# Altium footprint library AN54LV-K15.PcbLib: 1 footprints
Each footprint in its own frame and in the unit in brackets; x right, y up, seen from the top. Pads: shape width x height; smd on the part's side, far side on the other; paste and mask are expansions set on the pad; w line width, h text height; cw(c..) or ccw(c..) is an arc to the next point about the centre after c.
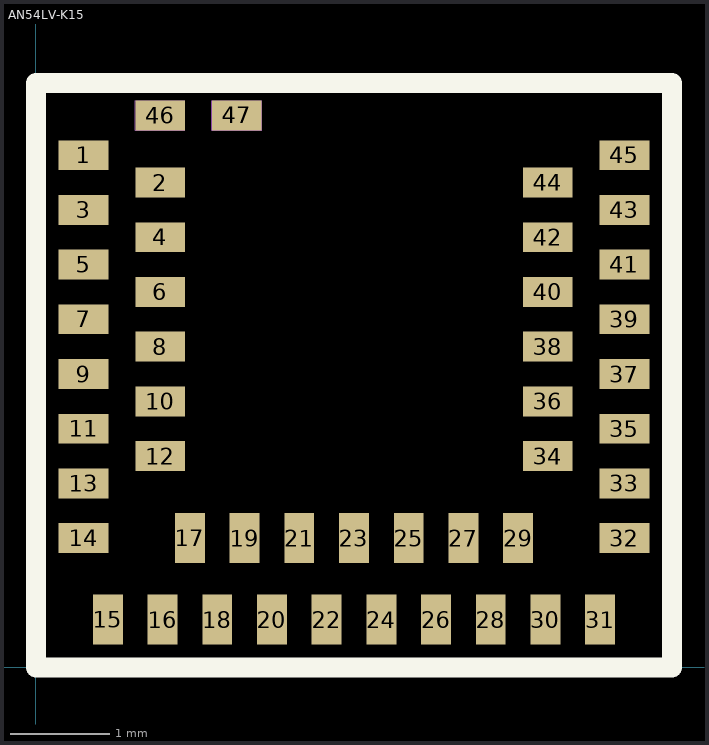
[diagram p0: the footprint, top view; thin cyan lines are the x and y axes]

## AN54LV-K15 [mm]
pads (47):
  rect 0.5x0.3 smd mask+0: 1(0.48,5.15) 2(1.25,4.875) 3(0.48,4.6) 4(1.25,4.325) 5(0.48,4.05) 6(1.25,3.775) 7(0.48,3.5) 8(1.25,3.225) 9(0.48,2.95) 10(1.25,2.675) 11(0.48,2.4) 12(1.25,2.125) 13(0.48,1.85) 14(0.48,1.3) 32(5.92,1.3) 33(5.92,1.85) 34(5.15,2.125) 35(5.92,2.4) 36(5.15,2.675) 37(5.92,2.95) 38(5.15,3.225) 39(5.92,3.5) 40(5.15,3.775) 41(5.92,4.05) 42(5.15,4.325) 43(5.92,4.6) 44(5.15,4.875) 45(5.92,5.15) 46(1.25,5.55) 47(2.02,5.55)
  rect 0.3x0.5 smd mask+0: 15(0.725,0.48) 16(1.275,0.48) 17(1.55,1.3) 18(1.825,0.48) 19(2.1,1.3) 20(2.375,0.48) 21(2.65,1.3) 22(2.925,0.48) 23(3.2,1.3) 24(3.475,0.48) 25(3.75,1.3) 26(4.025,0.48) 27(4.3,1.3) 28(4.575,0.48) 29(4.85,1.3) 30(5.125,0.48) 31(5.675,0.48)
Top Overlay:
  lines w0.2: 0,0 0,5.875 6.4,5.875 6.4,0 0,0
Mechanical 1:
  lines w0.05: 0,0 0,5.9 6.4,5.9 6.4,0 0,0
Mechanical 2:
  lines w0.01: 1,5.4 1.5,5.4 1.5,5.7 1,5.7 1,5.4 ; 1.77,5.4 2.27,5.4 2.27,5.7 1.77,5.7 1.77,5.4
Mechanical 9:
  lines w0.01: 0,0 0,5.9 6.4,5.9 6.4,0 0,0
